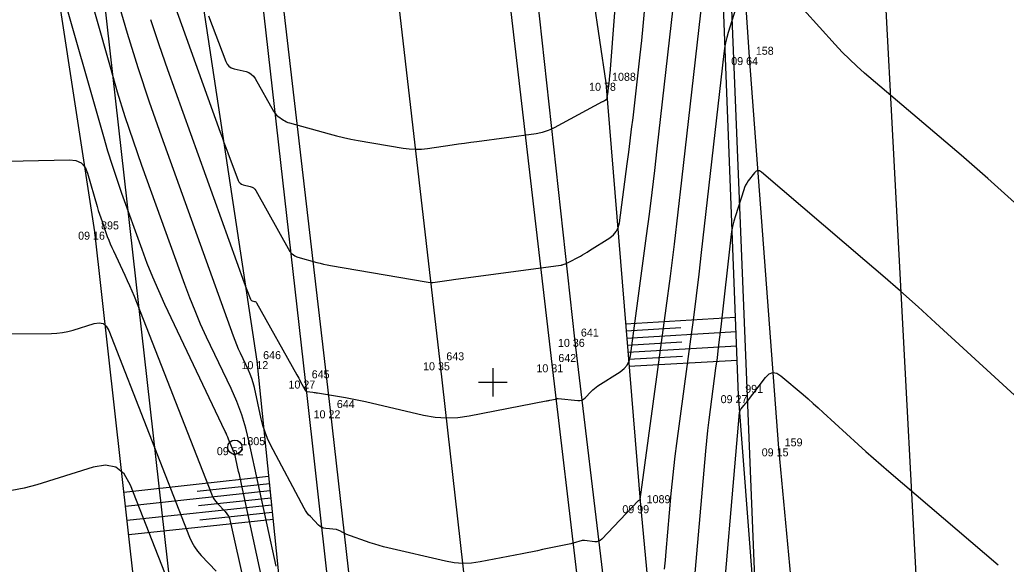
# Model space of a CAD drawing. Extents: x -711234 to -710007, y -1026313 to -1025448.
# Drawn here: x -710916.56 to -710882.04, y -1025931.37 to -1025912.31 of the extents above; entities that cross this region are included whole.
import ezdxf

# ---------------------------------------------------------------- set-up
doc = ezdxf.new("R2010")
doc.units = 0
for name, color, linetype in [('Ex_Major Contours', 7, 'Continuous'), ('Ex_Minor Contours', 7, 'Continuous'), ('Z_body', 7, 'Continuous'), ('Z_body_cisla', 7, 'Continuous'), ('Z_body_vysky_redukovane', 7, 'Continuous'), ('Z_hektometricka_sit', 7, 'Continuous'), ('Z_hrany_paty', 7, 'Continuous'), ('Z_katastr_hranice', 7, 'Continuous'), ('Z_komunikace', 7, 'Continuous'), ('Z_komunikace_osa', 7, 'Continuous'), ('Z_pole_rozhranni', 7, 'Continuous'), ('Z_technicke_srafy', 7, 'Continuous'), ('Z_vdz12_plna', 7, 'Continuous'), ('Z_vdz25_plna', 7, 'Continuous'), ('Z_zelen_jednotliva', 7, 'Continuous')]:
    doc.layers.add(name, color=color, linetype=linetype)

# ---------------------------------------------------------------- blocks, each defined once
blk = doc.blocks.new('POINT_DISPLAY')
blk.add_line((0, 0), (0, 0))
blk = doc.blocks.new('Z10001')
blk.add_circle((0, 0), 0.25)

msp = doc.modelspace()

# ---------------------------------------------------------------- linework, layer by layer
at = {"layer": 'Ex_Major Contours'}
for points in [[(-710892.446, -1025909.494), (-710893.395, -1025917.923), (-710893.525, -1025919.044), (-710893.66, -1025920.164), (-710893.802, -1025921.284), (-710893.95, -1025922.403), (-710894.853, -1025929.099), (-710894.855, -1025929.106), (-710894.858, -1025929.111), (-710894.862, -1025929.116), (-710894.867, -1025929.12), (-710894.89, -1025929.135), (-710894.896, -1025929.139), (-710894.902, -1025929.143), (-710894.907, -1025929.148), (-710894.912, -1025929.153), (-710896.187, -1025930.486), (-710896.241, -1025930.532), (-710896.301, -1025930.562), (-710896.366, -1025930.577), (-710896.436, -1025930.577), (-710896.794, -1025930.539), (-710896.835, -1025930.537), (-710896.876, -1025930.539), (-710896.916, -1025930.545), (-710896.956, -1025930.556), (-710897.115, -1025930.606), (-710897.154, -1025930.618), (-710897.194, -1025930.629), (-710897.235, -1025930.639), (-710897.275, -1025930.648), (-710898.262, -1025930.856), (-710898.44, -1025930.893), (-710898.619, -1025930.93), (-710898.797, -1025930.965), (-710898.976, -1025931), (-710900.442, -1025931.284), (-710900.746, -1025931.327), (-710901.049, -1025931.338), (-710901.351, -1025931.316), (-710901.653, -1025931.262), (-710903.671, -1025930.795), (-710903.827, -1025930.756), (-710903.982, -1025930.713), (-710904.136, -1025930.665), (-710904.289, -1025930.613), (-710905.143, -1025930.308), (-710905.171, -1025930.297), (-710905.2, -1025930.284), (-710905.227, -1025930.271), (-710905.254, -1025930.256), (-710905.361, -1025930.194), (-710905.389, -1025930.18), (-710905.417, -1025930.169), (-710905.446, -1025930.161), (-710905.477, -1025930.156), (-710905.85, -1025930.115), (-710905.92, -1025930.101), (-710905.985, -1025930.077), (-710906.044, -1025930.042), (-710906.098, -1025929.995), (-710906.387, -1025929.701), (-710906.45, -1025929.633), (-710906.507, -1025929.561), (-710906.559, -1025929.485), (-710906.605, -1025929.404), (-710907.779, -1025927.184), (-710907.884, -1025926.967), (-710907.974, -1025926.744), (-710908.049, -1025926.516), (-710908.107, -1025926.282), (-710908.346, -1025925.178), (-710908.384, -1025925.022), (-710908.432, -1025924.868), (-710908.488, -1025924.717), (-710908.553, -1025924.57), (-710908.83, -1025923.986), (-710908.898, -1025923.839), (-710908.961, -1025923.691), (-710909.022, -1025923.541), (-710909.078, -1025923.39), (-710911.599, -1025916.384), (-710912.015, -1025915.196), (-710912.411, -1025914.001), (-710912.786, -1025912.8), (-710913.067, -1025911.842)], [(-710920.727, -1025923.331), (-710915.447, -1025923.294), (-710915.255, -1025923.286), (-710915.065, -1025923.263), (-710914.877, -1025923.227), (-710914.691, -1025923.176), (-710913.953, -1025922.944), (-710913.783, -1025922.916), (-710913.641, -1025922.948), (-710913.527, -1025923.039), (-710913.443, -1025923.189), (-710910.612, -1025930.422), (-710910.535, -1025930.595), (-710910.441, -1025930.759), (-710910.333, -1025930.913), (-710910.209, -1025931.057), (-710909.681, -1025931.614)]]:
    msp.add_lwpolyline(points, dxfattribs=at)
at = {"layer": 'Ex_Minor Contours'}
for points in [[(-710907.588, -1025931.43), (-710908.524, -1025927.091), (-710908.643, -1025926.608), (-710908.789, -1025926.135), (-710908.962, -1025925.671), (-710909.162, -1025925.216), (-710910.018, -1025923.415), (-710910.226, -1025922.962), (-710910.423, -1025922.505), (-710910.608, -1025922.043), (-710910.783, -1025921.576), (-710912.28, -1025917.415), (-710912.579, -1025916.563), (-710912.862, -1025915.706), (-710913.131, -1025914.844), (-710913.386, -1025913.978), (-710916.371, -1025903.482)], [(-710909.947, -1025912.176), (-710909.346, -1025913.772), (-710909.299, -1025913.864), (-710909.236, -1025913.936), (-710909.156, -1025913.991), (-710909.059, -1025914.026), (-710908.638, -1025914.129), (-710908.54, -1025914.163), (-710908.454, -1025914.214), (-710908.382, -1025914.283), (-710908.322, -1025914.369), (-710907.679, -1025915.513), (-710907.647, -1025915.563), (-710907.611, -1025915.609), (-710907.569, -1025915.649), (-710907.523, -1025915.686), (-710907.328, -1025915.824), (-710907.278, -1025915.856), (-710907.226, -1025915.883), (-710907.172, -1025915.906), (-710907.116, -1025915.924), (-710905.728, -1025916.307), (-710905.477, -1025916.373), (-710905.224, -1025916.433), (-710904.97, -1025916.487), (-710904.715, -1025916.534), (-710903.141, -1025916.806), (-710902.927, -1025916.835), (-710902.712, -1025916.846), (-710902.498, -1025916.84), (-710902.283, -1025916.817), (-710901.423, -1025916.691), (-710901.208, -1025916.66), (-710900.992, -1025916.629), (-710900.777, -1025916.6), (-710900.562, -1025916.57), (-710898.49, -1025916.293), (-710898.433, -1025916.285), (-710898.378, -1025916.273), (-710898.323, -1025916.259), (-710898.268, -1025916.243), (-710898.051, -1025916.173), (-710897.997, -1025916.154), (-710897.944, -1025916.133), (-710897.893, -1025916.109), (-710897.842, -1025916.083), (-710896.16, -1025915.177), (-710896.144, -1025915.169), (-710896.128, -1025915.159), (-710896.112, -1025915.15), (-710896.097, -1025915.14), (-710896.035, -1025915.101), (-710896.021, -1025915.09), (-710896.011, -1025915.077), (-710896.003, -1025915.062), (-710895.999, -1025915.045), (-710895.969, -1025914.823), (-710895.964, -1025914.78), (-710895.958, -1025914.737), (-710895.953, -1025914.694), (-710895.948, -1025914.651), (-710895.921, -1025914.415), (-710895.915, -1025914.361), (-710895.91, -1025914.307), (-710895.905, -1025914.253), (-710895.901, -1025914.199), (-710895.228, -1025905.497)], [(-710907.002, -1025936.882), (-710908.798, -1025928.562), (-710908.823, -1025928.451), (-710908.847, -1025928.339), (-710908.871, -1025928.228), (-710908.896, -1025928.116), (-710909.042, -1025927.462), (-710909.044, -1025927.455), (-710909.047, -1025927.449), (-710909.05, -1025927.443), (-710909.055, -1025927.437), (-710909.075, -1025927.416), (-710909.08, -1025927.41), (-710909.084, -1025927.404), (-710909.088, -1025927.398), (-710909.091, -1025927.391), (-710909.248, -1025926.99), (-710909.276, -1025926.921), (-710909.305, -1025926.852), (-710909.335, -1025926.784), (-710909.366, -1025926.717), (-710911.475, -1025922.275), (-710911.693, -1025921.802), (-710911.898, -1025921.325), (-710912.092, -1025920.842), (-710912.274, -1025920.355), (-710912.979, -1025918.396), (-710913.151, -1025917.905), (-710913.315, -1025917.411), (-710913.47, -1025916.914), (-710913.616, -1025916.415), (-710915.163, -1025910.976)], [(-710911.982, -1025912.303), (-710911.69, -1025913.184), (-710911.383, -1025914.06), (-710908.699, -1025921.518), (-710908.677, -1025921.581), (-710908.654, -1025921.643), (-710908.631, -1025921.705), (-710908.608, -1025921.766), (-710908.484, -1025922.096), (-710908.474, -1025922.115), (-710908.461, -1025922.13), (-710908.445, -1025922.141), (-710908.425, -1025922.148), (-710908.338, -1025922.169), (-710908.318, -1025922.176), (-710908.3, -1025922.187), (-710908.285, -1025922.201), (-710908.273, -1025922.219), (-710906.855, -1025924.742), (-710906.826, -1025924.796), (-710906.796, -1025924.85), (-710906.767, -1025924.904), (-710906.738, -1025924.958), (-710906.573, -1025925.271), (-710906.569, -1025925.277), (-710906.565, -1025925.282), (-710906.561, -1025925.288), (-710906.556, -1025925.293), (-710906.537, -1025925.312), (-710906.532, -1025925.317), (-710906.526, -1025925.32), (-710906.52, -1025925.322), (-710906.514, -1025925.324), (-710906.295, -1025925.348), (-710906.257, -1025925.352), (-710906.218, -1025925.357), (-710906.18, -1025925.363), (-710906.141, -1025925.369), (-710905.159, -1025925.533), (-710904.983, -1025925.564), (-710904.807, -1025925.598), (-710904.632, -1025925.634), (-710904.458, -1025925.673), (-710902.423, -1025926.145), (-710902.025, -1025926.216), (-710901.627, -1025926.244), (-710901.228, -1025926.23), (-710900.828, -1025926.174), (-710898.14, -1025925.653), (-710898.106, -1025925.647), (-710898.071, -1025925.64), (-710898.037, -1025925.633), (-710898.002, -1025925.625), (-710897.811, -1025925.585), (-710897.803, -1025925.583), (-710897.796, -1025925.581), (-710897.788, -1025925.579), (-710897.78, -1025925.577), (-710897.75, -1025925.567), (-710897.742, -1025925.565), (-710897.734, -1025925.564), (-710897.726, -1025925.564), (-710897.718, -1025925.564), (-710897.033, -1025925.637), (-710896.959, -1025925.637), (-710896.892, -1025925.622), (-710896.83, -1025925.59), (-710896.774, -1025925.543), (-710896.562, -1025925.321), (-710896.508, -1025925.267), (-710896.45, -1025925.217), (-710896.39, -1025925.171), (-710896.327, -1025925.128), (-710895.543, -1025924.629), (-710895.406, -1025924.522), (-710895.302, -1025924.395), (-710895.23, -1025924.247), (-710895.19, -1025924.078), (-710894.623, -1025919.876), (-710894.523, -1025919.116), (-710894.426, -1025918.355), (-710894.334, -1025917.594), (-710894.246, -1025916.832), (-710893.69, -1025911.892)], [(-710911.168, -1025911.735), (-710909.545, -1025916.246), (-710909.479, -1025916.428), (-710909.412, -1025916.609), (-710909.345, -1025916.79), (-710909.277, -1025916.971), (-710908.915, -1025917.934), (-710908.887, -1025917.989), (-710908.849, -1025918.033), (-710908.8, -1025918.066), (-710908.742, -1025918.087), (-710908.488, -1025918.149), (-710908.429, -1025918.17), (-710908.377, -1025918.201), (-710908.333, -1025918.242), (-710908.297, -1025918.294), (-710907.101, -1025920.423), (-710907.086, -1025920.447), (-710907.069, -1025920.469), (-710907.049, -1025920.488), (-710907.027, -1025920.506), (-710906.933, -1025920.572), (-710906.909, -1025920.587), (-710906.884, -1025920.6), (-710906.858, -1025920.611), (-710906.831, -1025920.62), (-710906.166, -1025920.803), (-710906.046, -1025920.835), (-710905.925, -1025920.864), (-710905.803, -1025920.889), (-710905.681, -1025920.912), (-710902.34, -1025921.49), (-710902.26, -1025921.5), (-710902.18, -1025921.505), (-710902.099, -1025921.503), (-710902.019, -1025921.494), (-710901.696, -1025921.447), (-710901.615, -1025921.435), (-710901.535, -1025921.424), (-710901.454, -1025921.412), (-710901.373, -1025921.401), (-710897.624, -1025920.9), (-710897.604, -1025920.897), (-710897.584, -1025920.893), (-710897.564, -1025920.888), (-710897.545, -1025920.882), (-710897.467, -1025920.857), (-710897.448, -1025920.85), (-710897.429, -1025920.842), (-710897.41, -1025920.834), (-710897.392, -1025920.825), (-710896.94, -1025920.581), (-710896.859, -1025920.536), (-710896.778, -1025920.49), (-710896.699, -1025920.443), (-710896.621, -1025920.394), (-710895.91, -1025919.942), (-710895.781, -1025919.841), (-710895.682, -1025919.72), (-710895.613, -1025919.579), (-710895.575, -1025919.419), (-710895.296, -1025917.35), (-710895.243, -1025916.948), (-710895.192, -1025916.546), (-710895.144, -1025916.144), (-710895.097, -1025915.742), (-710894.849, -1025913.537), (-710894.794, -1025913.035), (-710894.744, -1025912.533), (-710894.699, -1025912.03)], [(-710891.506, -1025911.942), (-710891.765, -1025912.755), (-710891.818, -1025912.936), (-710891.862, -1025913.119), (-710891.897, -1025913.304), (-710891.922, -1025913.491), (-710892.708, -1025920.461), (-710892.795, -1025921.218), (-710892.886, -1025921.975), (-710892.982, -1025922.73), (-710893.082, -1025923.486), (-710893.575, -1025927.142), (-710893.632, -1025927.579), (-710893.683, -1025928.018), (-710893.729, -1025928.457), (-710893.769, -1025928.896), (-710893.944, -1025930.915), (-710893.973, -1025931.225), (-710894.008, -1025931.534)], [(-710881.752, -1025918.708), (-710882.212, -1025918.289), (-710882.677, -1025917.874), (-710883.145, -1025917.464), (-710883.617, -1025917.058), (-710886.995, -1025914.18), (-710887.264, -1025913.943), (-710887.524, -1025913.698), (-710887.777, -1025913.444), (-710888.021, -1025913.182), (-710889.119, -1025911.965)], [(-710920.792, -1025917.346), (-710914.814, -1025917.213), (-710914.588, -1025917.238), (-710914.407, -1025917.325), (-710914.271, -1025917.472), (-710914.18, -1025917.681), (-710913.847, -1025918.853), (-710913.808, -1025918.985), (-710913.767, -1025919.116), (-710913.724, -1025919.247), (-710913.678, -1025919.377), (-710913.492, -1025919.895), (-710913.444, -1025920.024), (-710913.392, -1025920.152), (-710913.338, -1025920.278), (-710913.28, -1025920.404), (-710912.878, -1025921.25), (-710912.793, -1025921.433), (-710912.712, -1025921.618), (-710912.633, -1025921.804), (-710912.558, -1025921.991), (-710909.852, -1025928.906), (-710909.811, -1025928.997), (-710909.763, -1025929.082), (-710909.706, -1025929.162), (-710909.642, -1025929.236), (-710909.368, -1025929.525), (-710909.305, -1025929.601), (-710909.254, -1025929.682), (-710909.215, -1025929.77), (-710909.188, -1025929.864), (-710906.59, -1025941.538)], [(-710880.224, -1025926.855), (-710884.516, -1025922.914), (-710885.124, -1025922.36), (-710885.738, -1025921.812), (-710886.357, -1025921.27), (-710886.98, -1025920.733), (-710890.603, -1025917.647), (-710890.669, -1025917.605), (-710890.732, -1025917.596), (-710890.791, -1025917.618), (-710890.846, -1025917.673), (-710891.062, -1025917.955), (-710891.113, -1025918.027), (-710891.157, -1025918.103), (-710891.194, -1025918.183), (-710891.224, -1025918.266), (-710891.515, -1025919.179), (-710891.568, -1025919.36), (-710891.612, -1025919.544), (-710891.647, -1025919.729), (-710891.672, -1025919.916), (-710892.027, -1025923.06), (-710892.068, -1025923.422), (-710892.112, -1025923.785), (-710892.158, -1025924.147), (-710892.206, -1025924.509), (-710892.401, -1025925.956), (-710892.448, -1025926.318), (-710892.49, -1025926.681), (-710892.528, -1025927.044), (-710892.562, -1025927.407), (-710893.01, -1025932.597)], [(-710892.081, -1025934.336), (-710891.366, -1025926.056), (-710891.36, -1025926.02), (-710891.349, -1025925.987), (-710891.333, -1025925.956), (-710891.312, -1025925.927), (-710891.216, -1025925.816), (-710891.192, -1025925.788), (-710891.169, -1025925.759), (-710891.146, -1025925.731), (-710891.124, -1025925.702), (-710890.456, -1025924.827), (-710890.333, -1025924.707), (-710890.203, -1025924.657), (-710890.065, -1025924.678), (-710889.92, -1025924.77), (-710889.144, -1025925.431), (-710888.966, -1025925.584), (-710888.789, -1025925.739), (-710888.614, -1025925.896), (-710888.44, -1025926.054), (-710887.214, -1025927.18), (-710886.951, -1025927.419), (-710886.686, -1025927.656), (-710886.418, -1025927.891), (-710886.148, -1025928.123), (-710882.321, -1025931.385)], [(-710911.373, -1025931.937), (-710912.681, -1025928.594), (-710912.898, -1025928.208), (-710913.189, -1025927.975), (-710913.552, -1025927.895), (-710913.989, -1025927.967), (-710915.963, -1025928.586), (-710916.398, -1025928.705), (-710916.837, -1025928.79)]]:
    msp.add_lwpolyline(points, dxfattribs=at)
at = {"layer": 'Z_hektometricka_sit'}
for p, q in [((-710900, -1025924.5), (-710900, -1025925.5)), ((-710900.5, -1025925), (-710899.5, -1025925))]:
    msp.add_line(p, q, dxfattribs=at)
at = {"layer": 'Z_hrany_paty'}
for p, q in [((-710898.93, -1025894.92), (-710896.05, -1025914.52)), ((-710910.78, -1025907.55), (-710908.26, -1025924.26)), ((-710891.4, -1025925.45), (-710892.06, -1025908.49)), ((-710896.05, -1025914.52), (-710894.84, -1025929.3)), ((-710908.26, -1025924.26), (-710906.37, -1025942.77)), ((-710890.17, -1025941.69), (-710891.4, -1025925.45)), ((-710894.84, -1025929.3), (-710893.47, -1025943.59))]:
    msp.add_line(p, q, dxfattribs=at)
at = {"layer": 'Z_katastr_hranice'}
msp.add_line((-710910.15, -1025942.26), (-710916.27, -1025887.83), dxfattribs=at)
for points in [[(-710889, -1025970.31), (-710889.68, -1025960.38), (-710892.53, -1025890.03), (-710898.37, -1025828.05), (-710905.02, -1025776.43), (-710911.59, -1025735.63)], [(-710888.58, -1025868.03), (-710883.69, -1025960.07), (-710882.89, -1025972.98)]]:
    msp.add_lwpolyline(points, dxfattribs=at)
at = {"layer": 'Z_komunikace'}
for p, q in [((-710898.93, -1025907.1), (-710897.14, -1025923.48)), ((-710908.54, -1025907.46), (-710906.57, -1025924.94)), ((-710897.14, -1025923.48), (-710894.99, -1025941.46)), ((-710906.57, -1025924.94), (-710904.59, -1025942.71))]:
    msp.add_line(p, q, dxfattribs=at)
at = {"layer": 'Z_komunikace_osa'}
msp.add_line((-710901.86, -1025924.3), (-710899.8, -1025942.36), dxfattribs=at)
at = {"layer": 'Z_pole_rozhranni'}
for p, q in [((-710891.98, -1025899.73), (-710891.03, -1025913.62)), ((-710913.93, -1025919.73), (-710916.42, -1025903.44)), ((-710891.03, -1025913.62), (-710890.01, -1025927.31)), ((-710912.22, -1025935.03), (-710913.93, -1025919.73)), ((-710890.01, -1025927.31), (-710888.77, -1025940.51))]:
    msp.add_line(p, q, dxfattribs=at)
at = {"layer": 'Z_technicke_srafy'}
for p, q in [((-710895.36, -1025922.95), (-710891.51, -1025922.72)), ((-710895.34, -1025923.2), (-710893.42, -1025923.08)), ((-710895.32, -1025923.45), (-710891.49, -1025923.22)), ((-710895.3, -1025923.7), (-710893.39, -1025923.58)), ((-710895.28, -1025923.95), (-710891.47, -1025923.72)), ((-710895.26, -1025924.19), (-710893.36, -1025924.08)), ((-710895.24, -1025924.44), (-710891.45, -1025924.22)), ((-710907.85, -1025928.3), (-710912.91, -1025928.85)), ((-710907.82, -1025928.55), (-710910.35, -1025928.82)), ((-710907.8, -1025928.8), (-710912.86, -1025929.34)), ((-710907.75, -1025929.3), (-710912.8, -1025929.84)), ((-710907.77, -1025929.05), (-710910.3, -1025929.32)), ((-710907.72, -1025929.55), (-710910.25, -1025929.82)), ((-710907.69, -1025929.8), (-710912.74, -1025930.34))]:
    msp.add_line(p, q, dxfattribs=at)
at = {"layer": 'Z_vdz12_plna'}
msp.add_line((-710903.8, -1025907.42), (-710901.86, -1025924.3), dxfattribs=at)
at = {"layer": 'Z_vdz25_plna'}
for p, q in [((-710907.85, -1025907.41), (-710905.69, -1025925.98)), ((-710899.93, -1025907.23), (-710897.94, -1025924.37)), ((-710897.94, -1025924.37), (-710895.87, -1025941.74)), ((-710905.69, -1025925.98), (-710903.8, -1025942.62))]:
    msp.add_line(p, q, dxfattribs=at)

# ---------------------------------------------------------------- block references
at = {"layer": 'Z_body'}
for p in [(-710891.03, -1025913.62), (-710896.05, -1025914.52), (-710913.93, -1025919.73), (-710897.14, -1025923.48), (-710908.26, -1025924.26), (-710901.86, -1025924.3), (-710897.94, -1025924.37), (-710906.57, -1025924.94), (-710891.4, -1025925.45), (-710905.69, -1025925.98), (-710909.03, -1025927.27), (-710890.01, -1025927.31), (-710894.84, -1025929.3)]:
    msp.add_blockref('POINT_DISPLAY', p, dxfattribs=at)
at = {"layer": 'Z_zelen_jednotliva'}
msp.add_blockref('Z10001', (-710909.03, -1025927.27), dxfattribs=at)

# ---------------------------------------------------------------- texts
at = {"layer": 'Z_body_cisla'}
for s, p in [('158', (-710890.8, -1025913.54)), ('1088', (-710895.83, -1025914.45)), ('895', (-710913.71, -1025919.65)), ('641', (-710896.92, -1025923.4)), ('646', (-710908.04, -1025924.19)), ('643', (-710901.63, -1025924.23)), ('642', (-710897.71, -1025924.29)), ('645', (-710906.34, -1025924.86)), ('991', (-710891.17, -1025925.37)), ('644', (-710905.46, -1025925.9)), ('1805', (-710908.8, -1025927.2)), ('159', (-710889.79, -1025927.24)), ('1089', (-710894.62, -1025929.23))]:
    msp.add_text(s, height=0.28, dxfattribs=at).set_placement(p)
at = {"layer": 'Z_body_vysky_redukovane'}
for s, p in [('09 64', (-710891.66, -1025913.9)), ('10 78', (-710896.633, -1025914.8)), ('09 16', (-710914.513, -1025920.01)), ('10 36', (-710897.723, -1025923.76)), ('10 12', (-710908.797, -1025924.54)), ('10 35', (-710902.443, -1025924.58)), ('10 31', (-710898.477, -1025924.65)), ('10 27', (-710907.153, -1025925.22)), ('09 27', (-710892.03, -1025925.73)), ('10 22', (-710906.273, -1025926.26)), ('09 52', (-710909.66, -1025927.55)), ('09 15', (-710890.593, -1025927.59)), ('09 99', (-710895.47, -1025929.58))]:
    msp.add_text(s, height=0.28, dxfattribs=at).set_placement(p)

doc.saveas('drawing.dxf')
